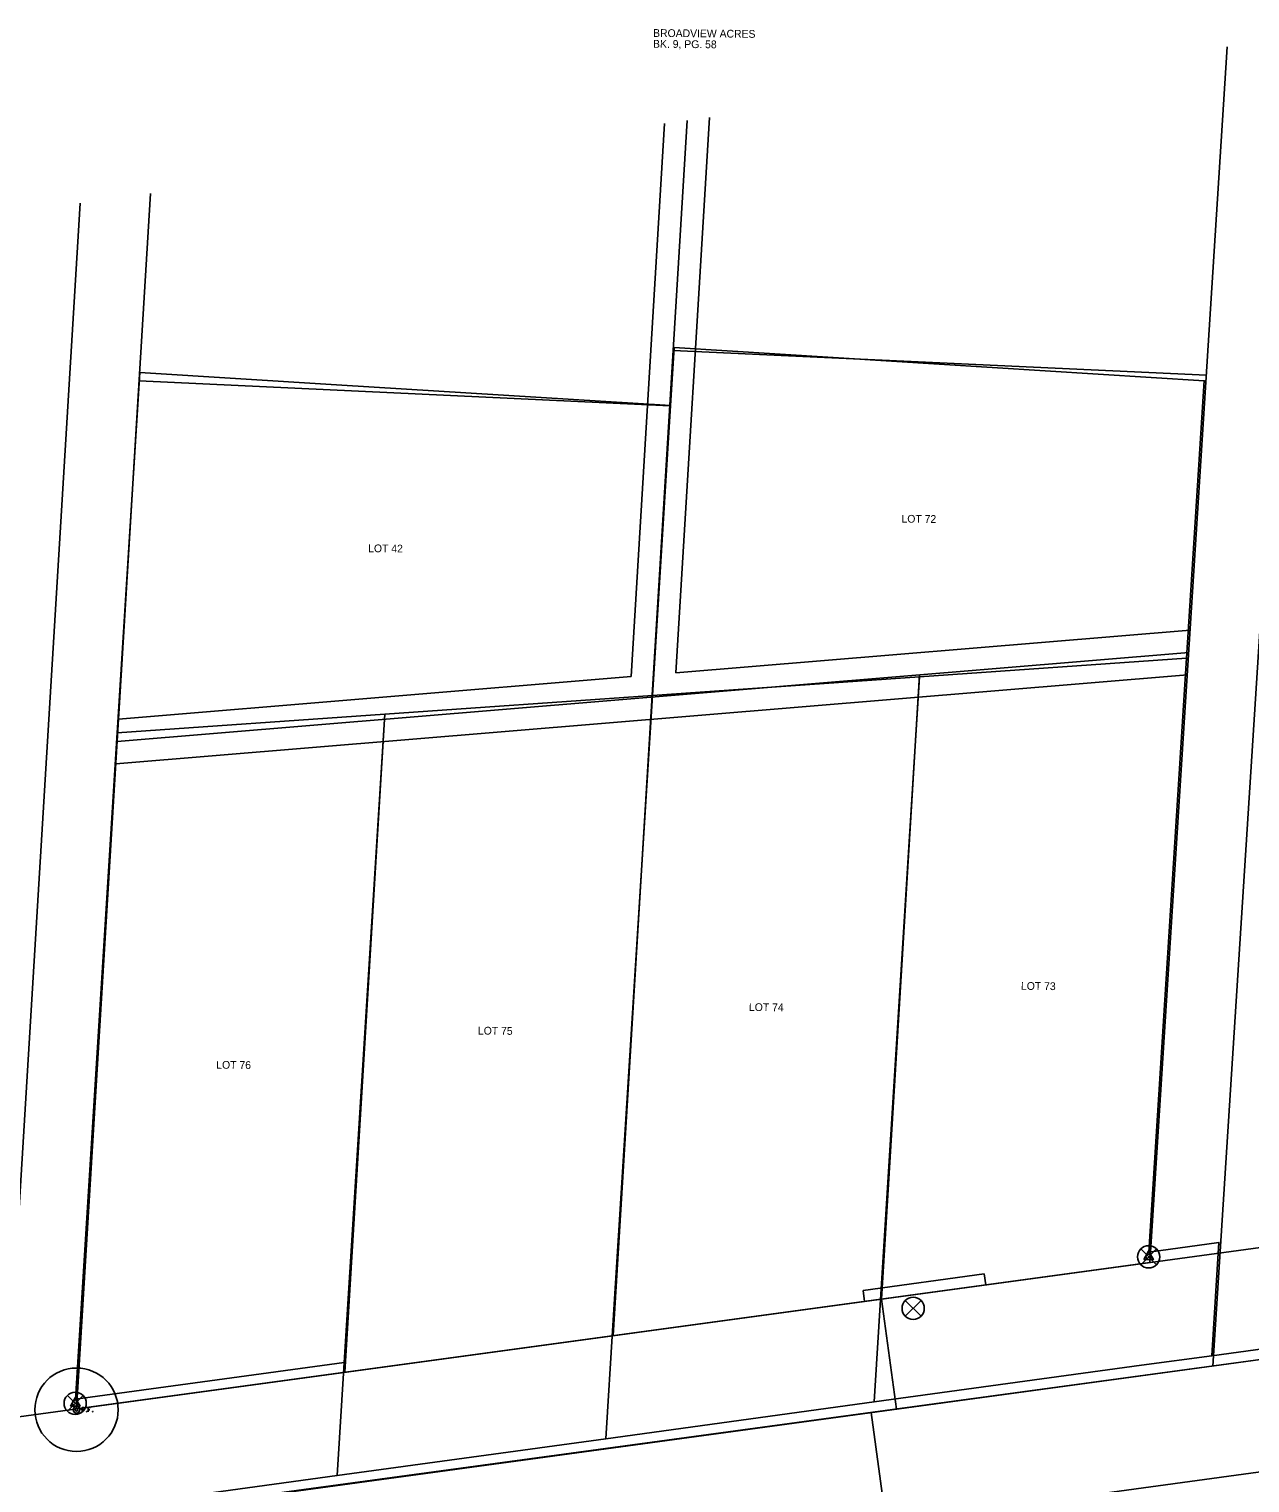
# Model space of a CAD drawing. Extents: x 1532954 to 1577849, y 698998 to 706606.
# Drawn here: x 1573393 to 1573832, y 703101 to 703624 of the extents above; entities that cross this region are included whole.
import ezdxf

# ---------------------------------------------------------------- set-up
doc = ezdxf.new("R2010")
doc.units = 0
for name, color, linetype in [('Default', 7, 'Continuous'), ('DV_X_Property_Line', 7, 'Continuous'), ('RW_P_Esmt_TMP', 7, 'Continuous'), ('RW_X_CL', 7, 'Continuous'), ('RW_X_Esmt_SH', 7, 'Continuous'), ('RW_X_Esmt_U', 7, 'Continuous'), ('RW_X_Fee_RW', 7, 'Continuous'), ('SC_Scratch1', 7, 'Continuous'), ('SC_Scratch10', 7, 'Continuous'), ('SC_Scratch2', 7, 'Continuous'), ('SC_Scratch3', 7, 'Continuous'), ('SC_Scratch9', 7, 'Continuous'), ('SV_Control_Point', 7, 'Continuous'), ('SV_X_Mon_Cells_Found', 7, 'Continuous')]:
    doc.layers.add(name, color=color, linetype=linetype)

msp = doc.modelspace()

# ---------------------------------------------------------------- linework, layer by layer
at = {"layer": 'Default'}
for p, q in [((1573792.94, 703185.34), (1573798.6, 703179.69)), ((1573792.94, 703179.69), (1573798.6, 703185.34)), ((1573795.77, 703182.51), (1573795.77, 703182.51)), ((1573708.21, 703166.8), (1573713.86, 703161.14)), ((1573708.21, 703161.14), (1573713.86, 703166.8)), ((1573711.04, 703163.97), (1573711.04, 703163.97)), ((1573406.69, 703132.65), (1573412.35, 703126.99)), ((1573406.69, 703126.99), (1573412.35, 703132.65)), ((1573409.52, 703129.82), (1573409.52, 703129.82))]:
    msp.add_line(p, q, dxfattribs=at)
for centre in [(1573795.77, 703182.51), (1573711.04, 703163.97), (1573409.52, 703129.82)]:
    msp.add_circle(centre, 4, dxfattribs=at)
at = {"layer": 'DV_X_Property_Line'}
for p, q in [((1573603.1, 703154.14), (1573629.7, 703591.44)), ((1573624.67, 703508.72), (1573816.56, 703499.82)), ((1573432.48, 703497.75), (1573623.46, 703488.82)), ((1573424.59, 703367.99), (1573810.21, 703400.02)), ((1573699.67, 703167.3), (1573713.33, 703391.97)), ((1573506.53, 703140.98), (1573520.83, 703375.99))]:
    msp.add_line(p, q, dxfattribs=at)
at = {"layer": 'RW_P_Esmt_TMP'}
for p, q in [((1573693, 703170.43), (1573736.59, 703176.37)), ((1573737.13, 703172.41), (1573736.59, 703176.37)), ((1573693.54, 703166.47), (1573693, 703170.43))]:
    msp.add_line(p, q, dxfattribs=at)
at = {"layer": 'RW_X_CL'}
for p, q in [((1573818.91, 703143.18), (1573849.35, 703621.38)), ((1573382.25, 703083.67), (1573411.32, 703561.68))]:
    msp.add_line(p, q, dxfattribs=at)
at = {"layer": 'RW_X_Esmt_SH'}
msp.add_line((1571959, 702849.32), (1574870.56, 703246.15), dxfattribs=at)
at = {"layer": 'RW_X_Esmt_U'}
for p, q in [((1573625.63, 703392.72), (1573637.78, 703592.55)), ((1573609.52, 703391.38), (1573621.62, 703590.34)), ((1573625.63, 703392.72), (1573810.72, 703408.09)), ((1573424.1, 703359.92), (1573809.7, 703391.95)), ((1573425.08, 703376.06), (1573609.52, 703391.38))]:
    msp.add_line(p, q, dxfattribs=at)
at = {"layer": 'RW_X_Fee_RW'}
for p, q in [((1573796.24, 703180.46), (1573824.08, 703617.94)), ((1573409.98, 703127.82), (1573436.58, 703565.12)), ((1573409.98, 703127.82), (1573796.24, 703180.46))]:
    msp.add_line(p, q, dxfattribs=at)
at = {"layer": 'SC_Scratch1'}
for points in [[(1573815.79, 703497.78), (1573815.79, 703497.78), (1573809.43, 703397.98), (1573713.34, 703391.26), (1573617.25, 703384.53), (1573623.78, 703488.83), (1573623.78, 703488.83), (1573625.09, 703509.73), (1573625.09, 703509.73)], [(1573623.78, 703488.83), (1573623.78, 703488.83), (1573617.25, 703384.53), (1573520.93, 703377.79), (1573424.62, 703371.06), (1573432.75, 703500.8), (1573503.54, 703496.36)], [(1573699.54, 703171), (1573713.34, 703391.26), (1573809.43, 703397.98), (1573795.81, 703184.2), (1573821.08, 703187.67), (1573818.48, 703146.94), (1573793.21, 703143.47), (1573696.98, 703130.28)], [(1573699.54, 703171), (1573696.98, 703130.28), (1573600.48, 703117.05), (1573603.03, 703157.77), (1573617.25, 703384.53), (1573713.34, 703391.26)], [(1573600.48, 703117.05), (1573503.76, 703103.79), (1573506.31, 703144.51), (1573520.93, 703377.79), (1573617.25, 703384.53), (1573603.03, 703157.77)], [(1573424.62, 703371.06), (1573520.93, 703377.79), (1573506.31, 703144.51), (1573409.59, 703131.25)]]:
    msp.add_lwpolyline(points, close=True, dxfattribs=at)
msp.add_lwpolyline([(1573381.77, 703087.06), (1573407.03, 703090.53), (1573503.76, 703103.79), (1573600.48, 703117.05), (1573696.98, 703130.28), (1573793.21, 703143.47), (1573818.48, 703146.94), (1573843.76, 703150.4), (1573940.5, 703163.67), (1574012.63, 703173.56), (1574009.55, 703132.76), (1573992.57, 702907.55), (1573992.57, 702907.55), (1574153.57, 702895.41), (1574152.55, 702881.84), (1574277.72, 702872.4), (1574506.31, 702855.16), (1574480.3, 702510.33), (1574373.41, 701092.97)], dxfattribs=at)
at = {"layer": 'SC_Scratch10'}
for p, q in [((1571190.11, 702825.26), (1574958.12, 703338.82)), ((1571190.11, 702825.26), (1574958.12, 703338.82)), ((1571190.11, 702825.26), (1574958.12, 703338.82)), ((1571195.51, 702785.63), (1574963.52, 703299.19)), ((1571200.91, 702745.99), (1574968.92, 703259.55))]:
    msp.add_line(p, q, dxfattribs=at)
at = {"layer": 'SC_Scratch2'}
for p, q in [((1573824.08, 703617.94), (1573796.24, 703180.46)), ((1573849.35, 703621.38), (1573818.91, 703143.18)), ((1573603.1, 703154.14), (1573629.7, 703591.44)), ((1573625.63, 703392.72), (1573637.78, 703592.55)), ((1573609.52, 703391.38), (1573621.62, 703590.34)), ((1573409.98, 703127.82), (1573436.58, 703565.12)), ((1573382.25, 703083.67), (1573411.32, 703561.68)), ((1573624.67, 703508.72), (1573816.56, 703499.82)), ((1573432.48, 703497.75), (1573623.46, 703488.82)), ((1573625.63, 703392.72), (1573810.72, 703408.09)), ((1573424.59, 703367.99), (1573810.21, 703400.02)), ((1573424.1, 703359.92), (1573809.7, 703391.95)), ((1573699.67, 703167.3), (1573713.33, 703391.97)), ((1573425.08, 703376.06), (1573609.52, 703391.38)), ((1573506.53, 703140.98), (1573520.83, 703375.99)), ((1573796.24, 703180.46), (1573409.98, 703127.82)), ((1574037.66, 703173), (1573356.99, 703080.23))]:
    msp.add_line(p, q, dxfattribs=at)
at = {"layer": 'SC_Scratch3'}
msp.add_line((1574533, 703240.3), (1572963.42, 703027.05), dxfattribs=at)
at = {"layer": 'SC_Scratch9'}
for p, q in [((1573699.67, 703167.3), (1573705.07, 703127.67)), ((1573701.37, 703086.79), (1573695.97, 703126.43))]:
    msp.add_line(p, q, dxfattribs=at)
msp.add_circle((1573409.99, 703127.47), 15, dxfattribs=at)
at = {"layer": 'SV_Control_Point'}
for p, q in [((1573795.77, 703182.51), (1573795.77, 703182.51)), ((1573409.52, 703129.82), (1573409.52, 703129.82))]:
    msp.add_line(p, q, dxfattribs=at)
for points in [[(1573794.04, 703181.51), (1573795.77, 703184.51), (1573797.5, 703181.51)], [(1573407.79, 703128.82), (1573409.52, 703131.82), (1573411.25, 703128.82)]]:
    msp.add_lwpolyline(points, close=True, dxfattribs=at)
for centre in [(1573795.77, 703182.51), (1573409.52, 703129.82)]:
    msp.add_circle(centre, 1, dxfattribs=at)
at = {"layer": 'SV_X_Mon_Cells_Found'}
for points in [[(1573411.99, 703126.67), (1573411.99, 703128.27), (1573412.52, 703128.27), (1573412.57, 703128.26), (1573412.65, 703128.23), (1573412.68, 703128.21), (1573412.71, 703128.18), (1573412.76, 703128.12), (1573412.79, 703128.06), (1573412.81, 703127.96), (1573412.81, 703127.8), (1573412.8, 703127.75), (1573412.78, 703127.68), (1573412.74, 703127.59), (1573412.69, 703127.55), (1573412.66, 703127.53), (1573412.6, 703127.5), (1573412.52, 703127.49), (1573411.99, 703127.49)], [(1573413.63, 703126.88), (1573413.68, 703126.88), (1573413.72, 703126.86), (1573413.75, 703126.81), (1573413.75, 703126.75), (1573413.72, 703126.7), (1573413.68, 703126.67), (1573413.63, 703126.67), (1573413.6, 703126.7), (1573413.56, 703126.75), (1573413.56, 703126.81), (1573413.6, 703126.86), (1573413.63, 703126.88)], [(1573415, 703128.27), (1573414.24, 703128.27), (1573414.24, 703126.67)], [(1573414.24, 703127.49), (1573414.78, 703127.49)], [(1573415.78, 703126.88), (1573415.83, 703126.88), (1573415.87, 703126.86), (1573415.9, 703126.81), (1573415.9, 703126.75), (1573415.87, 703126.7), (1573415.83, 703126.67), (1573415.78, 703126.67), (1573415.75, 703126.7), (1573415.71, 703126.75), (1573415.71, 703126.81), (1573415.75, 703126.86), (1573415.78, 703126.88)]]:
    msp.add_lwpolyline(points, dxfattribs=at)
for radius in [1.2, 0.495]:
    msp.add_circle((1573409.99, 703127.47), radius, dxfattribs=at)

# ---------------------------------------------------------------- texts
at = {"layer": 'SC_Scratch2'}
for s, p in [('BROADVIEW ACRES', (1573617.46, 703621.55)), ('BK. 9, PG. 58', (1573617.43, 703617.65)), ('LOT 72', (1573706.83, 703446.74)), ('LOT 42', (1573514.92, 703436.1)), ('LOT 73', (1573749.82, 703278.62)), ('LOT 74', (1573651.94, 703271)), ('LOT 75', (1573554.42, 703262.52)), ('LOT 76', (1573460.27, 703250.23))]:
    msp.add_text(s, height=2.8, rotation=359.4613, dxfattribs=at).set_placement(p)

doc.saveas('drawing.dxf')
